Omron CX-Programmer project NuevoProyecto (CX-Programmer 9.50)

# PLC NewPLC1: CP1L-E EM

## Program P20_2 (cyclic task 0)
Local symbols
A 0.04 BOOL  ; Selección tolva A
B 0.05 BOOL  ; Selección tolva B
De 0.07 BOOL  ; Selección CIN3 derecha
EVA 100.04 BOOL  ; Electroválvula tolva A
EVB 100.05 BOOL  ; Electroválvula tolva B
Em 15.00 BOOL  ; Emergencia memorizada
Etapa_0 10.00 BOOL
Etapa_1 10.01 BOOL
Etapa_10 10.10 BOOL
Etapa_11 10.11 BOOL
Etapa_2 10.02 BOOL
Etapa_20 20.00 BOOL
Etapa_21 20.01 BOOL
Etapa_22 20.02 BOOL
Etapa_23 20.03 BOOL
Etapa_24 20.04 BOOL
Etapa_3 10.03 BOOL
Etapa_4 10.04 BOOL
Etapa_5 10.05 BOOL
Etapa_6 10.06 BOOL
Etapa_7 10.07 BOOL
Etapa_8 10.08 BOOL
Etapa_9 10.09 BOOL
H_1 100.06 BOOL  ; Lámpara marcha
H_2 100.07 BOOL  ; Lámpara paro
H_3 101.00 BOOL  ; Lámpara emergencia
H_4 101.01 BOOL  ; Lámpara RT1
H_5 101.02 BOOL  ; Lámpara RT2
H_6 101.03 BOOL  ; Lámpara RT3
Iz 0.06 BOOL  ; Selección CIN3 izquierda
K1 100.00 BOOL  ; Contactor CIN1
K2 100.01 BOOL  ; Contactor CIN2
K3D 100.03 BOOL  ; Contactor derecha CIN3
K3I 100.02 BOOL  ; Contactor izquierda CIN3
PE 0.02 BOOL  ; Pulsador de emergencia
PM 0.00 BOOL  ; Pulsador de marcha
PP 0.01 BOOL  ; Pulsador de paro
PR 0.03 BOOL  ; Pulsador de rearme
RT 15.01 BOOL  ; RT=RT1+RT2+RT3
RT1 0.08 BOOL  ; Relé térmico CIN1
RT2 0.09 BOOL  ; Relé térmico CIN2
RT3 0.10 BOOL  ; Relé térmico CIN3
RTm 15.02 BOOL  ; Relés térmicos memorizados

### Section Sección1_Programa_principal
; Etapas 0 ... 10

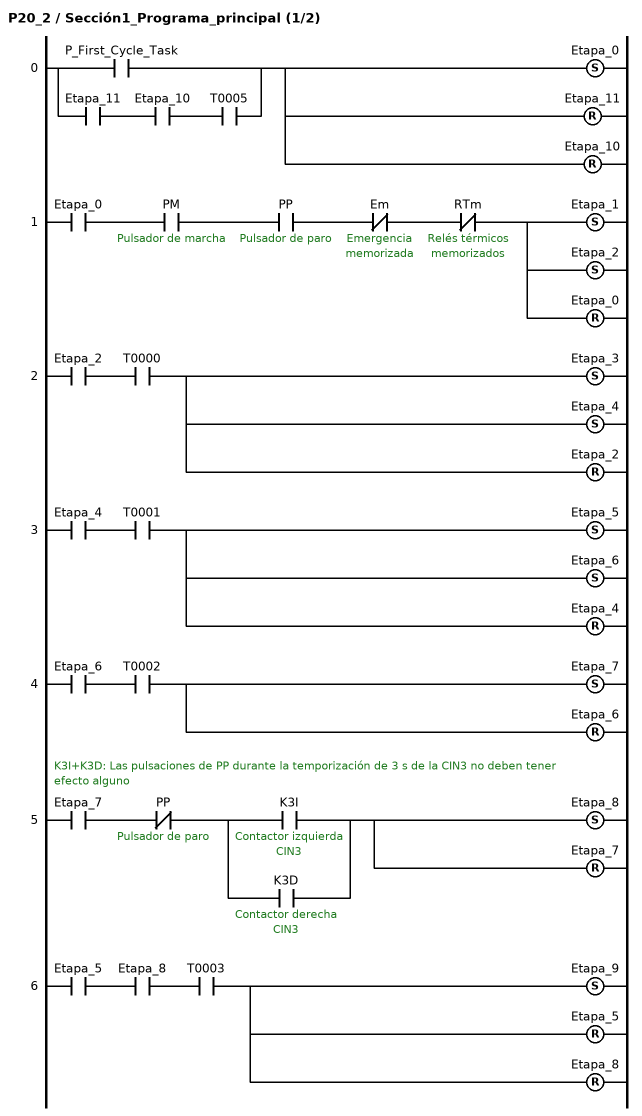
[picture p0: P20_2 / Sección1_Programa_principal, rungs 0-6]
; rung 0
LD P_First_Cycle_Task
LD Etapa_11
AND Etapa_10
AND T0005
ORLD
SET Etapa_0
RSET Etapa_11
RSET Etapa_10
; rung 1
LD Etapa_0
AND PM  ; Pulsador de marcha
AND PP  ; Pulsador de paro
ANDNOT Em  ; Emergencia memorizada
ANDNOT RTm  ; Relés térmicos memorizados
SET Etapa_1
SET Etapa_2
RSET Etapa_0
; rung 2
LD Etapa_2
AND T0000
SET Etapa_3
SET Etapa_4
RSET Etapa_2
; rung 3
LD Etapa_4
AND T0001
SET Etapa_5
SET Etapa_6
RSET Etapa_4
; rung 4
LD Etapa_6
AND T0002
SET Etapa_7
RSET Etapa_6
; rung 5: K3I+K3D: Las pulsaciones de PP durante la temporización de 3 s de la CIN3 no deben tener efecto alguno
LD Etapa_7
ANDNOT PP  ; Pulsador de paro
LD K3I  ; Contactor izquierda CIN3
OR K3D  ; Contactor derecha CIN3
ANDLD
SET Etapa_8
RSET Etapa_7
; rung 6
LD Etapa_5
AND Etapa_8
AND T0003
SET Etapa_9
RSET Etapa_5
RSET Etapa_8

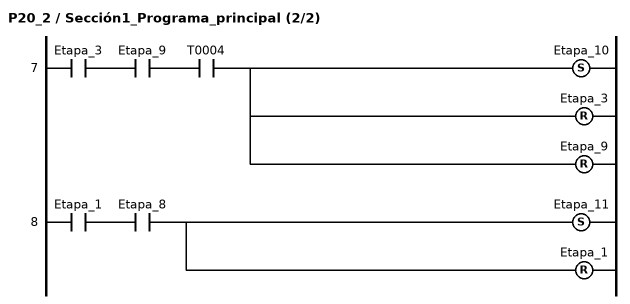
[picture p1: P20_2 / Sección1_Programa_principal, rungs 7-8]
; rung 7
LD Etapa_3
AND Etapa_9
AND T0004
SET Etapa_10
RSET Etapa_3
RSET Etapa_9
; rung 8
LD Etapa_1
AND Etapa_8
SET Etapa_11
RSET Etapa_1

### Section Sección2_Disparo_térmicos
; Etapas 20 ... 24

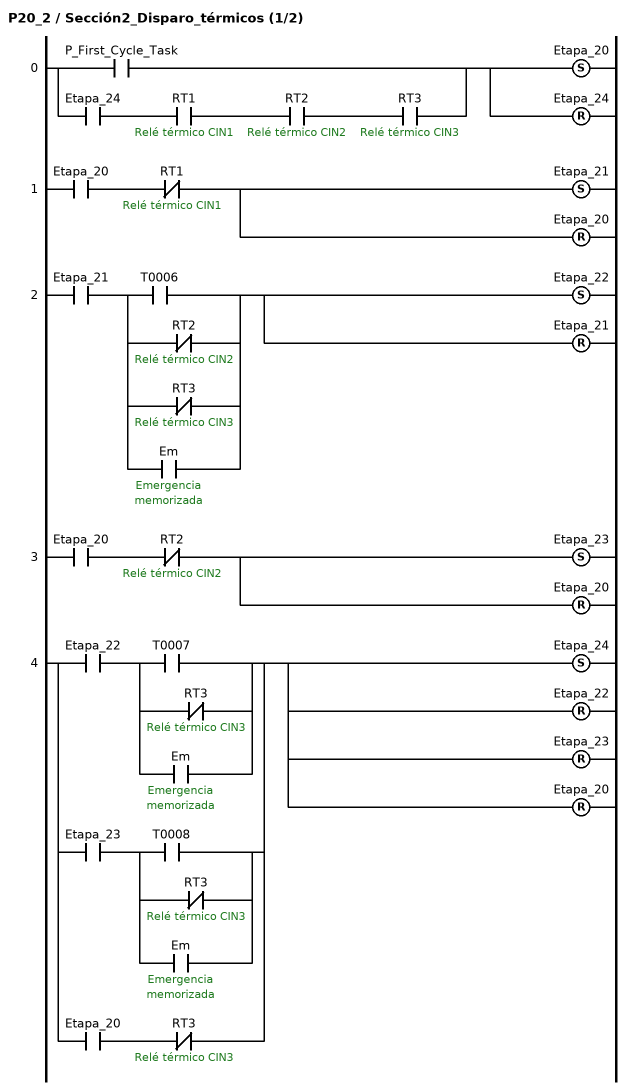
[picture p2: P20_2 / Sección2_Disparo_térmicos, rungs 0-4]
; rung 0
LD P_First_Cycle_Task
LD Etapa_24
AND RT1  ; Relé térmico CIN1
AND RT2  ; Relé térmico CIN2
AND RT3  ; Relé térmico CIN3
ORLD
SET Etapa_20
RSET Etapa_24
; rung 1
LD Etapa_20
ANDNOT RT1  ; Relé térmico CIN1
SET Etapa_21
RSET Etapa_20
; rung 2
LD Etapa_21
LD T0006
ORNOT RT2  ; Relé térmico CIN2
ORNOT RT3  ; Relé térmico CIN3
OR Em  ; Emergencia memorizada
ANDLD
SET Etapa_22
RSET Etapa_21
; rung 3
LD Etapa_20
ANDNOT RT2  ; Relé térmico CIN2
SET Etapa_23
RSET Etapa_20
; rung 4
LD Etapa_22
LD T0007
ORNOT RT3  ; Relé térmico CIN3
OR Em  ; Emergencia memorizada
ANDLD
LD Etapa_23
LD T0008
ORNOT RT3  ; Relé térmico CIN3
OR Em  ; Emergencia memorizada
ANDLD
ORLD
LD Etapa_20
ANDNOT RT3  ; Relé térmico CIN3
ORLD
SET Etapa_24
RSET Etapa_22
RSET Etapa_23
RSET Etapa_20

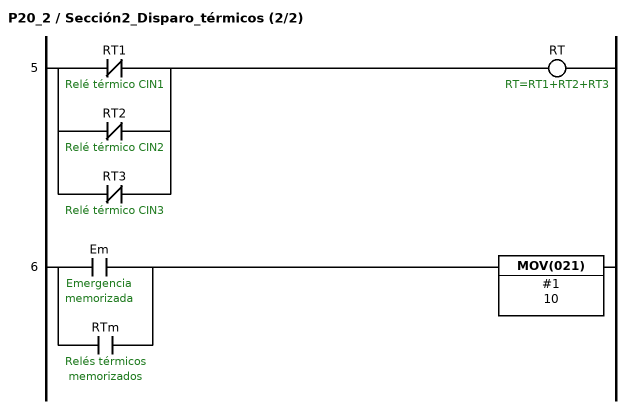
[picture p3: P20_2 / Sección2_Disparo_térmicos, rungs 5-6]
; rung 5
LDNOT RT1  ; Relé térmico CIN1
ORNOT RT2  ; Relé térmico CIN2
ORNOT RT3  ; Relé térmico CIN3
OUT RT  ; RT=RT1+RT2+RT3
; rung 6
LD Em  ; Emergencia memorizada
OR RTm  ; Relés térmicos memorizados
MOV(021) #1 10  // Si Em = 1 o RTm = 1 entonces X0 = 1, X1 = X2 = ... = X10 = 0 (Inicialización del primer GRAFCET)

### Section Sección3_Temporizadores

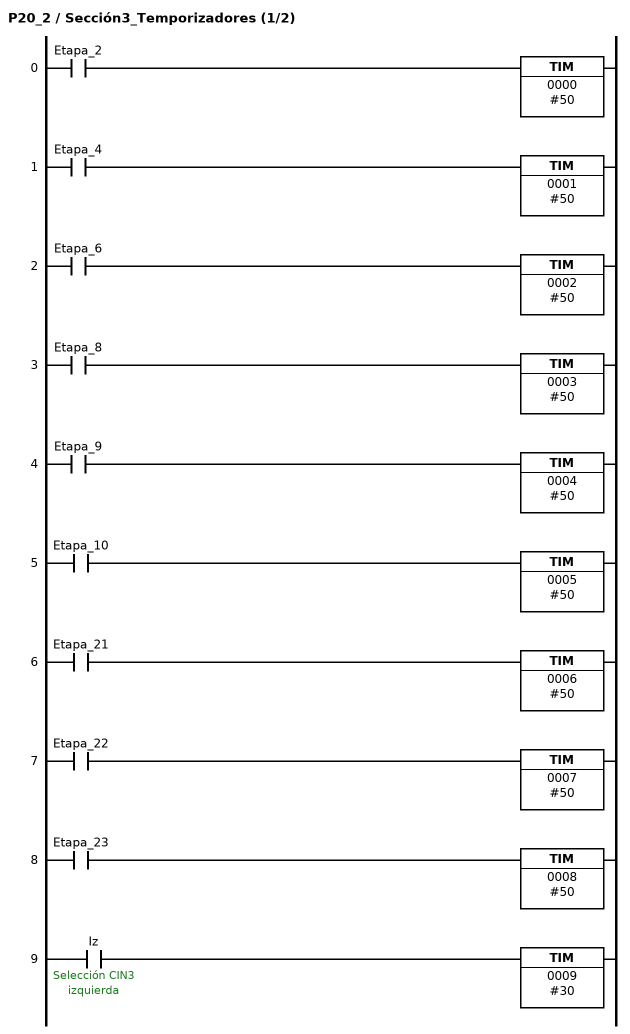
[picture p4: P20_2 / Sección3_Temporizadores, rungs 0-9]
; rung 0
LD Etapa_2
TIM 0000 #50
; rung 1
LD Etapa_4
TIM 0001 #50
; rung 2
LD Etapa_6
TIM 0002 #50
; rung 3
LD Etapa_8
TIM 0003 #50
; rung 4
LD Etapa_9
TIM 0004 #50
; rung 5
LD Etapa_10
TIM 0005 #50
; rung 6
LD Etapa_21
TIM 0006 #50
; rung 7
LD Etapa_22
TIM 0007 #50
; rung 8
LD Etapa_23
TIM 0008 #50
; rung 9
LD Iz  ; Selección CIN3 izquierda
TIM 0009 #30

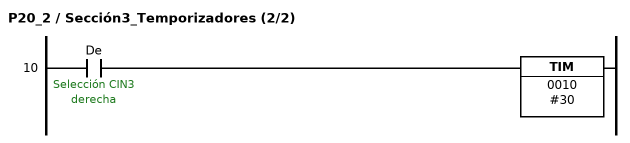
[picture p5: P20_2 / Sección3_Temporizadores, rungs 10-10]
; rung 10
LD De  ; Selección CIN3 derecha
TIM 0010 #30

### Section Sección4_Memorizaciones

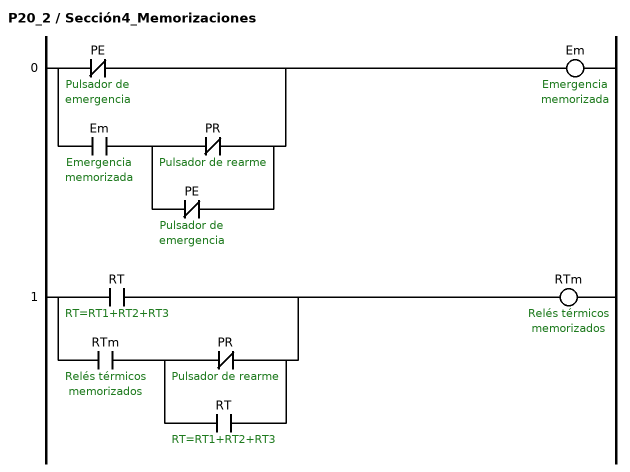
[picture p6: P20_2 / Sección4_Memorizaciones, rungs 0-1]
; rung 0
LDNOT PE  ; Pulsador de emergencia
LD Em  ; Emergencia memorizada
LDNOT PR  ; Pulsador de rearme
ORNOT PE  ; Pulsador de emergencia
ANDLD
ORLD
OUT Em  ; Emergencia memorizada  // Em=PE+Em·(PR·PE')'=PE+Em·(PR'+PE)
; rung 1
LD RT  ; RT=RT1+RT2+RT3
LD RTm  ; Relés térmicos memorizados
LDNOT PR  ; Pulsador de rearme
OR RT  ; RT=RT1+RT2+RT3
ANDLD
ORLD
OUT RTm  ; Relés térmicos memorizados  // RTm=RT+RTm·(PR·RT')'=RT+RTm·(PR'+RT)

### Section Sección5_Salidas

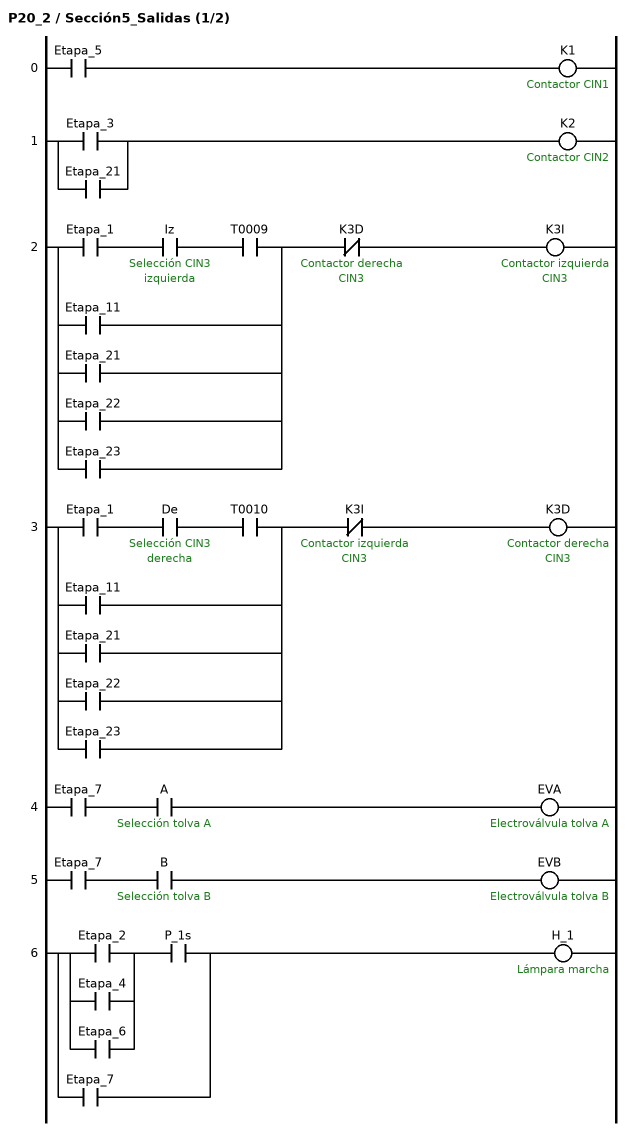
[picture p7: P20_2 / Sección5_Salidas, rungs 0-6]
; rung 0
LD Etapa_5
OUT K1  ; Contactor CIN1
; rung 1
LD Etapa_3
OR Etapa_21
OUT K2  ; Contactor CIN2
; rung 2
LD Etapa_1
AND Iz  ; Selección CIN3 izquierda
AND T0009
OR Etapa_11
OR Etapa_21
OR Etapa_22
OR Etapa_23
ANDNOT K3D  ; Contactor derecha CIN3
OUT K3I  ; Contactor izquierda CIN3
; rung 3
LD Etapa_1
AND De  ; Selección CIN3 derecha
AND T0010
OR Etapa_11
OR Etapa_21
OR Etapa_22
OR Etapa_23
ANDNOT K3I  ; Contactor izquierda CIN3
OUT K3D  ; Contactor derecha CIN3
; rung 4
LD Etapa_7
AND A  ; Selección tolva A
OUT EVA  ; Electroválvula tolva A
; rung 5
LD Etapa_7
AND B  ; Selección tolva B
OUT EVB  ; Electroválvula tolva B
; rung 6
LD Etapa_2
OR Etapa_4
OR Etapa_6
AND P_1s
OR Etapa_7
OUT H_1  ; Lámpara marcha

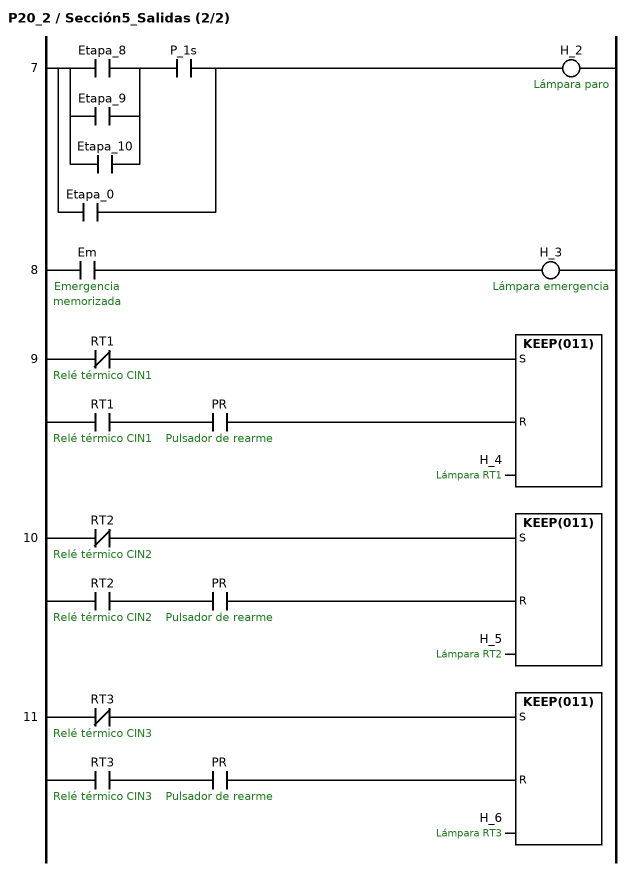
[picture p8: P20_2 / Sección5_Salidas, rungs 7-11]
; rung 7
LD Etapa_8
OR Etapa_9
OR Etapa_10
AND P_1s
OR Etapa_0
OUT H_2  ; Lámpara paro
; rung 8
LD Em  ; Emergencia memorizada
OUT H_3  ; Lámpara emergencia
; rung 9
LDNOT RT1  ; Relé térmico CIN1
LD RT1  ; Relé térmico CIN1
AND PR  ; Pulsador de rearme
KEEP(011) H_4  ; Lámpara RT1
; rung 10
LDNOT RT2  ; Relé térmico CIN2
LD RT2  ; Relé térmico CIN2
AND PR  ; Pulsador de rearme
KEEP(011) H_5  ; Lámpara RT2
; rung 11
LDNOT RT3  ; Relé térmico CIN3
LD RT3  ; Relé térmico CIN3
AND PR  ; Pulsador de rearme
KEEP(011) H_6  ; Lámpara RT3

### Section Sección6_END
; rung 0: Fin de programa
END(001)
